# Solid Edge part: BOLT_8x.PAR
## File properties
Author: nperez
Template: SCHRAUBE_DIN_EN_24014_M_8X_40.par
Last saved by: rkriggs
Revision: 18
Application: Solid Edge
Accuracy: 0.99
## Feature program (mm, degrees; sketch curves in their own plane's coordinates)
body "unnamed Body 1"
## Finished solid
Body 1: solid body, 16 faces, 26 edges, 20 vertices.
  Faces by surface: plane 11, cylinder 3, cone 2
  Edges by curve: line 12, circle 8, spline 6
Bounding box of the edges (mm): 13.000 x 15.011 x 45.300, from (-6.5, -7.5056, 0) to (6.5, 7.5056, 45.3).
Cylindrical faces by radius (mm): R3.233 x1, R4 x2
Conical faces (half-angle, radius in mm at the cone's reference point): 45 deg R25.1735 x1, 45 deg R25.6227 x1
Planar faces by outward normal: +x 1, +z 3, -x 1, -z 2, oblique 4
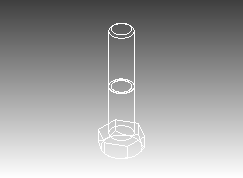
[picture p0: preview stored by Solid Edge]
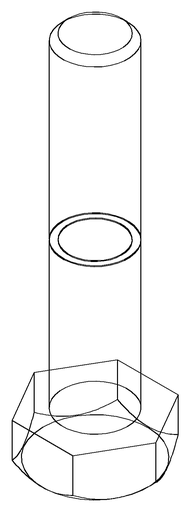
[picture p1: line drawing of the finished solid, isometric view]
